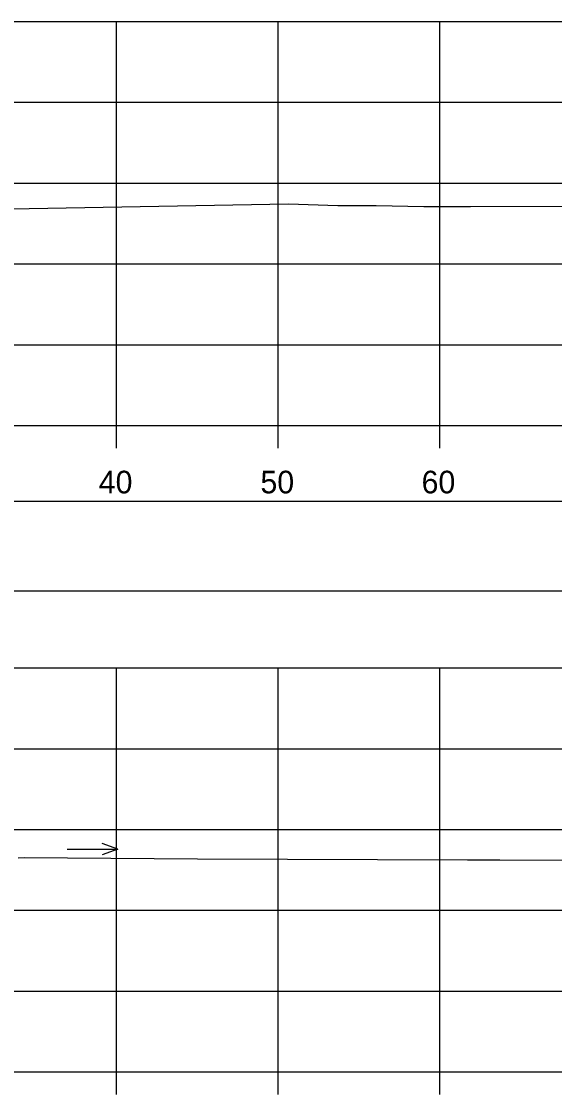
# Model space of a CAD drawing. Extents: x 1369627 to 1374022, y 380035 to 398173.
# Drawn here: x 1372132.7 to 1372165.6, y 380274.7 to 380341.1 of the extents above; entities that cross this region are included whole.
import ezdxf

# ---------------------------------------------------------------- set-up
doc = ezdxf.new("R2010")
doc.units = 0
for name, color, linetype in [('Default', 7, 'Continuous'), ('R_Axis', 7, 'Continuous'), ('R_Axis Annot', 7, 'Continuous'), ('R_Exist Surface', 7, 'Continuous'), ('R_Grid', 7, 'Continuous'), ('R_Water Annot', 7, 'Continuous')]:
    doc.layers.add(name, color=color, linetype=linetype)

msp = doc.modelspace()

# ---------------------------------------------------------------- linework, layer by layer
at = {"layer": 'Default'}
msp.add_lwpolyline([(1371948.53, 380305.871), (1372248.53, 380305.871), (1372248.53, 380311.393), (1371948.53, 380311.393)], close=True, dxfattribs=at)
at = {"layer": 'R_Axis'}
for p, q in [((1371948.53, 380316.097), (1372248.53, 380316.097)), ((1372138.53, 380314.697), (1372138.53, 380316.097)), ((1372148.53, 380314.697), (1372148.53, 380316.097)), ((1372158.53, 380314.697), (1372158.53, 380316.097)), ((1371948.53, 380276.097), (1372248.53, 380276.097)), ((1372138.53, 380274.697), (1372138.53, 380276.097)), ((1372148.53, 380274.697), (1372148.53, 380276.097)), ((1372158.53, 380274.697), (1372158.53, 380276.097))]:
    msp.add_line(p, q, dxfattribs=at)
at = {"layer": 'R_Exist Surface'}
for points in [[(1372120.189, 380329.257), (1372133.142, 380329.52), (1372149.172, 380329.813), (1372152.228, 380329.715), (1372154.605, 380329.715), (1372157.558, 380329.657), (1372160.432, 380329.654), (1372183.265, 380329.727)], [(1372132.459, 380289.353), (1372132.833, 380289.36), (1372143.559, 380289.276), (1372160.248, 380289.219), (1372162.209, 380289.213), (1372162.247, 380289.213), (1372180.789, 380289.159)]]:
    msp.add_lwpolyline(points, dxfattribs=at)
at = {"layer": 'R_Grid'}
for p, q in [((1371948.53, 380341.097), (1372248.53, 380341.097)), ((1372138.53, 380316.097), (1372138.53, 380341.097)), ((1372148.53, 380316.097), (1372148.53, 380341.097)), ((1372158.53, 380316.097), (1372158.53, 380341.097)), ((1371948.53, 380336.097), (1372248.53, 380336.097)), ((1371948.53, 380331.097), (1372248.53, 380331.097)), ((1371948.53, 380326.097), (1372248.53, 380326.097)), ((1371948.53, 380321.097), (1372248.53, 380321.097)), ((1371948.53, 380316.097), (1372248.53, 380316.097)), ((1371948.53, 380301.097), (1372248.53, 380301.097)), ((1372138.53, 380276.097), (1372138.53, 380301.097)), ((1372148.53, 380276.097), (1372148.53, 380301.097)), ((1372158.53, 380276.097), (1372158.53, 380301.097)), ((1371948.53, 380296.097), (1372248.53, 380296.097)), ((1371948.53, 380291.097), (1372248.53, 380291.097)), ((1371948.53, 380286.097), (1372248.53, 380286.097)), ((1371948.53, 380281.097), (1372248.53, 380281.097)), ((1371948.53, 380276.097), (1372248.53, 380276.097))]:
    msp.add_line(p, q, dxfattribs=at)
at = {"layer": 'R_Water Annot'}
for p, q in [((1372138.621, 380289.878), (1372137.659, 380290.228)), ((1372135.479, 380289.878), (1372138.621, 380289.878)), ((1372138.621, 380289.878), (1372137.659, 380289.528))]:
    msp.add_line(p, q, dxfattribs=at)

# ---------------------------------------------------------------- texts
at = {"layer": 'R_Axis Annot'}
for s, p in [('40', (1372137.444, 380311.897)), ('50', (1372147.444, 380311.897)), ('60', (1372157.411, 380311.897))]:
    msp.add_text(s, height=1.4, dxfattribs=at).set_placement(p)

doc.saveas('drawing.dxf')
